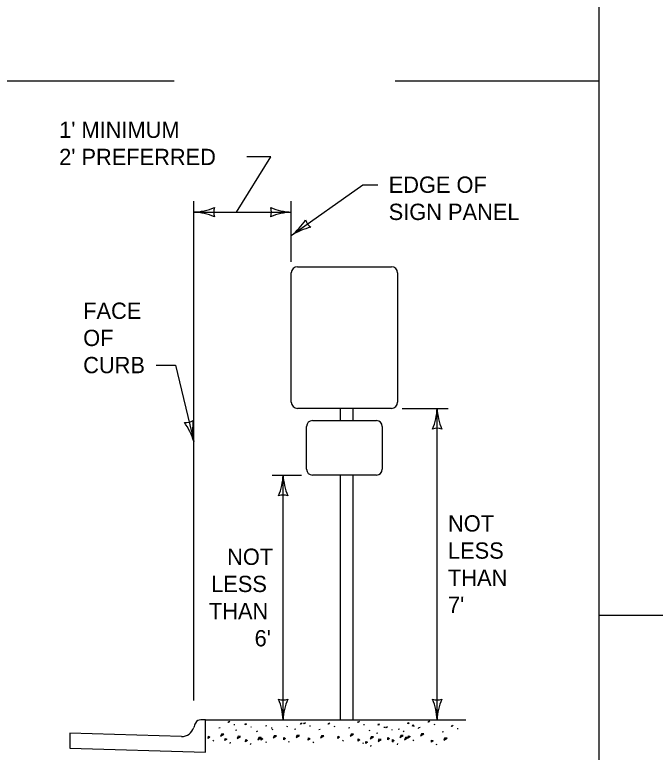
# Model space of a CAD drawing. Extents: x 49991.4 to 50021, y 49987.6 to 50011.4.
# Drawn here: x 50005.916 to 50008.274, y 49993.569 to 49996.284 of the extents above; entities that cross this region are included whole.
import ezdxf

# ---------------------------------------------------------------- set-up
doc = ezdxf.new("R2010")
doc.units = 0
for name, color, linetype in [('Level 1', 7, 'Continuous'), ('Level 2', 7, 'Continuous'), ('Level 3', 7, 'Continuous')]:
    doc.layers.add(name, color=color, linetype=linetype)

msp = doc.modelspace()

# ---------------------------------------------------------------- linework, layer by layer
at = {"layer": 'Level 1'}
for p, q in [((50006.9565, 49995.3563), (50007.3026, 49995.3563)), ((50006.934, 49994.8576), (50006.934, 49995.3338)), ((50007.3251, 49995.3338), (50007.3251, 49994.8576)), ((50007.3026, 49994.8351), (50006.9565, 49994.8351)), ((50007.1151, 49994.7902), (50007.1151, 49994.8351)), ((50007.1613, 49994.7902), (50007.1613, 49994.8351)), ((50006.9901, 49994.611), (50006.9901, 49994.7687)), ((50007.0116, 49994.7902), (50007.2476, 49994.7902)), ((50007.2691, 49994.7687), (50007.2691, 49994.611)), ((50007.2476, 49994.5895), (50007.0116, 49994.5895)), ((50007.1151, 49993.6882), (50007.1151, 49994.5895)), ((50007.1613, 49993.6882), (50007.1613, 49994.5895)), ((50006.6179, 49993.6882), (50006.6009, 49993.6882)), ((50006.6179, 49993.6882), (50007.5762, 49993.6882)), ((50006.6179, 49993.5697), (50006.6179, 49993.6882)), ((50006.7019, 49993.6784), (50006.7039, 49993.6831)), ((50006.7039, 49993.6831), (50006.7063, 49993.6795)), ((50007.1792, 49993.6784), (50007.1813, 49993.6831)), ((50007.1813, 49993.6831), (50007.1837, 49993.6795)), ((50007.4384, 49993.68), (50007.4404, 49993.6847)), ((50007.4429, 49993.681), (50007.4384, 49993.68)), ((50007.4404, 49993.6847), (50007.4429, 49993.681)), ((50006.6719, 49993.6588), (50006.6673, 49993.6573)), ((50006.7063, 49993.6795), (50006.7019, 49993.6784)), ((50006.7248, 49993.6688), (50006.7253, 49993.6724)), ((50006.7635, 49993.6704), (50006.7655, 49993.6751)), ((50006.7679, 49993.6715), (50006.7635, 49993.6704)), ((50006.7655, 49993.6751), (50006.7679, 49993.6715)), ((50006.7864, 49993.6608), (50006.7869, 49993.6644)), ((50006.8439, 49993.6667), (50006.8394, 49993.6656)), ((50006.8623, 49993.6561), (50006.8628, 49993.6597)), ((50006.9192, 49993.6625), (50006.9197, 49993.6661)), ((50006.9501, 49993.6541), (50006.9455, 49993.6525)), ((50006.9681, 49993.6721), (50006.9701, 49993.6768)), ((50006.9726, 49993.6732), (50006.9681, 49993.6721)), ((50006.9701, 49993.6768), (50006.9726, 49993.6732)), ((50006.9801, 49993.6736), (50006.9821, 49993.6784)), ((50006.9846, 49993.6747), (50006.9801, 49993.6736)), ((50006.9821, 49993.6784), (50006.9846, 49993.6747)), ((50007.003, 49993.6641), (50007.0035, 49993.6677)), ((50007.0702, 49993.6721), (50007.0722, 49993.6768)), ((50007.0747, 49993.6732), (50007.0702, 49993.6721)), ((50007.0722, 49993.6768), (50007.0747, 49993.6732)), ((50007.0931, 49993.6625), (50007.0936, 49993.6661)), ((50007.1493, 49993.6588), (50007.1446, 49993.6573)), ((50007.1837, 49993.6795), (50007.1792, 49993.6784)), ((50007.2021, 49993.6688), (50007.2026, 49993.6724)), ((50007.2536, 49993.6688), (50007.2556, 49993.6735)), ((50007.258, 49993.6699), (50007.2536, 49993.6688)), ((50007.2556, 49993.6735), (50007.258, 49993.6699)), ((50007.2765, 49993.6592), (50007.277, 49993.6629)), ((50007.2819, 49993.6593), (50007.284, 49993.6641)), ((50007.2864, 49993.6604), (50007.2819, 49993.6593)), ((50007.284, 49993.6641), (50007.2864, 49993.6604)), ((50007.3326, 49993.6541), (50007.328, 49993.6525)), ((50007.3626, 49993.6736), (50007.3646, 49993.6784)), ((50007.3671, 49993.6747), (50007.3626, 49993.6736)), ((50007.3646, 49993.6784), (50007.3671, 49993.6747)), ((50007.3799, 49993.6656), (50007.382, 49993.6704)), ((50007.3844, 49993.6667), (50007.3799, 49993.6656)), ((50007.382, 49993.6704), (50007.3844, 49993.6667)), ((50007.3855, 49993.6641), (50007.386, 49993.6677)), ((50007.4028, 49993.6561), (50007.4033, 49993.6597)), ((50007.4084, 49993.6604), (50007.4038, 49993.6588)), ((50007.4613, 49993.6704), (50007.4618, 49993.674)), ((50007.5238, 49993.6641), (50007.5258, 49993.6688)), ((50007.5283, 49993.6652), (50007.5238, 49993.6641)), ((50007.5258, 49993.6688), (50007.5283, 49993.6652)), ((50007.5467, 49993.6545), (50007.5472, 49993.6581)), ((50006.5296, 49993.6265), (50006.118, 49993.6388)), ((50006.118, 49993.6388), (50006.118, 49993.5846)), ((50006.6282, 49993.6199), (50006.6287, 49993.6282)), ((50006.6287, 49993.6282), (50006.6345, 49993.6249)), ((50006.6765, 49993.6358), (50006.6732, 49993.6279)), ((50006.6732, 49993.6279), (50006.6854, 49993.6356)), ((50006.6854, 49993.6356), (50006.6765, 49993.6358)), ((50006.7335, 49993.6508), (50006.7289, 49993.6493)), ((50006.7381, 49993.6278), (50006.7348, 49993.6199)), ((50006.7348, 49993.6199), (50006.747, 49993.6276)), ((50006.747, 49993.6276), (50006.7381, 49993.6278)), ((50006.8094, 49993.6461), (50006.8048, 49993.6445)), ((50006.8663, 49993.6525), (50006.8617, 49993.651)), ((50006.8709, 49993.6295), (50006.8676, 49993.6216)), ((50006.8676, 49993.6216), (50006.8798, 49993.6293)), ((50006.8798, 49993.6293), (50006.8709, 49993.6295)), ((50006.9547, 49993.6311), (50006.9514, 49993.6232)), ((50006.9514, 49993.6232), (50006.9636, 49993.6308)), ((50006.9636, 49993.6308), (50006.9547, 49993.6311)), ((50007.0402, 49993.6525), (50007.0356, 49993.651)), ((50007.0448, 49993.6295), (50007.0416, 49993.6216)), ((50007.0416, 49993.6216), (50007.0537, 49993.6293)), ((50007.0537, 49993.6293), (50007.0448, 49993.6295)), ((50007.1056, 49993.6199), (50007.1061, 49993.6282)), ((50007.1061, 49993.6282), (50007.1119, 49993.6249)), ((50007.1539, 49993.6358), (50007.1506, 49993.6279)), ((50007.1506, 49993.6279), (50007.1627, 49993.6356)), ((50007.1627, 49993.6356), (50007.1539, 49993.6358)), ((50007.2236, 49993.6493), (50007.219, 49993.6477)), ((50007.252, 49993.6398), (50007.2474, 49993.6382)), ((50007.3049, 49993.6498), (50007.3053, 49993.6534)), ((50007.3372, 49993.6311), (50007.334, 49993.6232)), ((50007.334, 49993.6232), (50007.3461, 49993.6308)), ((50007.3461, 49993.6308), (50007.3372, 49993.6311)), ((50007.35, 49993.6461), (50007.3454, 49993.6445)), ((50007.3648, 49993.6215), (50007.3653, 49993.6297)), ((50007.3711, 49993.6265), (50007.3648, 49993.6215)), ((50007.3653, 49993.6297), (50007.3711, 49993.6265)), ((50007.413, 49993.6374), (50007.4098, 49993.6295)), ((50007.4098, 49993.6295), (50007.4219, 49993.6371)), ((50007.4219, 49993.6371), (50007.413, 49993.6374)), ((50007.4938, 49993.6445), (50007.4892, 49993.643)), ((50006.6345, 49993.6249), (50006.6282, 49993.6199)), ((50006.647, 49993.6137), (50006.6455, 49993.6095)), ((50006.6898, 49993.6119), (50006.6903, 49993.6202)), ((50006.6962, 49993.6169), (50006.6898, 49993.6119)), ((50006.6903, 49993.6202), (50006.6962, 49993.6169)), ((50006.7086, 49993.6057), (50006.7071, 49993.6015)), ((50006.7658, 49993.6072), (50006.7663, 49993.6154)), ((50006.7721, 49993.6122), (50006.7658, 49993.6072)), ((50006.7663, 49993.6154), (50006.7721, 49993.6122)), ((50006.7846, 49993.601), (50006.783, 49993.5968)), ((50006.814, 49993.6231), (50006.8108, 49993.6152)), ((50006.8108, 49993.6152), (50006.8229, 49993.6228)), ((50006.8229, 49993.6228), (50006.814, 49993.6231)), ((50006.8226, 49993.6136), (50006.8231, 49993.6219)), ((50006.829, 49993.6186), (50006.8226, 49993.6136)), ((50006.8231, 49993.6219), (50006.829, 49993.6186)), ((50006.8414, 49993.6074), (50006.8399, 49993.6032)), ((50006.9065, 49993.6152), (50006.9069, 49993.6234)), ((50006.9128, 49993.6202), (50006.9065, 49993.6152)), ((50006.9069, 49993.6234), (50006.9128, 49993.6202)), ((50006.9252, 49993.609), (50006.9237, 49993.6048)), ((50006.9966, 49993.6136), (50006.997, 49993.6219)), ((50007.0029, 49993.6186), (50006.9966, 49993.6136)), ((50006.997, 49993.6219), (50007.0029, 49993.6186)), ((50007.0154, 49993.6074), (50007.0138, 49993.6032)), ((50007.1119, 49993.6249), (50007.1056, 49993.6199)), ((50007.1244, 49993.6137), (50007.1228, 49993.6095)), ((50007.1799, 49993.6103), (50007.1804, 49993.6186)), ((50007.1862, 49993.6153), (50007.1799, 49993.6103)), ((50007.1804, 49993.6186), (50007.1862, 49993.6153)), ((50007.1987, 49993.6042), (50007.1972, 49993.5999)), ((50007.2083, 49993.6009), (50007.2088, 49993.6091)), ((50007.2146, 49993.6059), (50007.2083, 49993.6009)), ((50007.2088, 49993.6091), (50007.2146, 49993.6059)), ((50007.2282, 49993.6262), (50007.2249, 49993.6183)), ((50007.2249, 49993.6183), (50007.2371, 49993.626)), ((50007.2371, 49993.626), (50007.2282, 49993.6262)), ((50007.2566, 49993.6168), (50007.2533, 49993.6089)), ((50007.2533, 49993.6089), (50007.2654, 49993.6165)), ((50007.2654, 49993.6165), (50007.2566, 49993.6168)), ((50007.289, 49993.6152), (50007.2895, 49993.6234)), ((50007.2953, 49993.6202), (50007.289, 49993.6152)), ((50007.2895, 49993.6234), (50007.2953, 49993.6202)), ((50007.3078, 49993.609), (50007.3062, 49993.6048)), ((50007.3063, 49993.6072), (50007.3068, 49993.6154)), ((50007.3126, 49993.6122), (50007.3063, 49993.6072)), ((50007.3068, 49993.6154), (50007.3126, 49993.6122)), ((50007.3251, 49993.601), (50007.3235, 49993.5968)), ((50007.3546, 49993.6231), (50007.3513, 49993.6152)), ((50007.3513, 49993.6152), (50007.3634, 49993.6228)), ((50007.3634, 49993.6228), (50007.3546, 49993.6231)), ((50007.3836, 49993.6153), (50007.382, 49993.6111)), ((50007.4501, 49993.6056), (50007.4506, 49993.6139)), ((50007.4565, 49993.6106), (50007.4501, 49993.6056)), ((50007.4506, 49993.6139), (50007.4565, 49993.6106)), ((50007.4689, 49993.5994), (50007.4674, 49993.5952)), ((50007.4984, 49993.6215), (50007.4951, 49993.6136)), ((50007.4951, 49993.6136), (50007.5073, 49993.6213)), ((50007.5073, 49993.6213), (50007.4984, 49993.6215)), ((50006.118, 49993.5846), (50006.6179, 49993.5697)), ((50007.2271, 49993.5947), (50007.2255, 49993.5904))]:
    msp.add_line(p, q, dxfattribs=at)
for centre, radius, start, end in [((50006.9565, 49995.3338), 0.0225, 90, 180), ((50007.3026, 49995.3338), 0.0225, 0, 90), ((50006.9565, 49994.8576), 0.0225, 180, 270), ((50007.3026, 49994.8576), 0.0225, 270, 0), ((50007.0116, 49994.7687), 0.0215, 90, 180), ((50007.2476, 49994.7687), 0.0215, 0, 90), ((50007.0116, 49994.611), 0.0215, 180, 270), ((50007.2476, 49994.611), 0.0215, 270, 0), ((50006.5993, 49993.6689), 0.0194, 85.3754, 156.6889), ((50006.5292, 49993.6742), 0.0477, 270.4937, 342.4535), ((50006.6257, 49993.6489), 0.0521, 148.469, 167.8949)]:
    msp.add_arc(centre, radius, start, end, dxfattribs=at)
at = {"layer": 'Level 3'}
for p, q in [((50008.0668, 49998.9992), (50008.0668, 49994.0732)), ((50005.0025, 49996.0407), (50006.5025, 49996.0407)), ((50007.3168, 49996.0407), (50008.0668, 49996.0407)), ((50006.7318, 49995.5574), (50006.8582, 49995.7607)), ((50006.8582, 49995.7607), (50006.7707, 49995.7607)), ((50006.934, 49995.4712), (50007.1971, 49995.6585)), ((50007.1971, 49995.6585), (50007.2525, 49995.6585)), ((50006.5747, 49993.7598), (50006.5747, 49995.5974)), ((50006.934, 49995.3751), (50006.934, 49995.5974)), ((50006.5747, 49995.5574), (50006.934, 49995.5574)), ((50006.4359, 49994.9945), (50006.5079, 49994.9945)), ((50006.5079, 49994.9945), (50006.5747, 49994.713)), ((50007.3426, 49994.8351), (50007.5109, 49994.8351)), ((50007.4709, 49993.6882), (50007.4709, 49994.8351)), ((50006.8638, 49994.5895), (50006.9716, 49994.5895)), ((50006.9038, 49993.6882), (50006.9038, 49994.5895)), ((50008.0668, 49994.0732), (50016.7501, 49994.0732)), ((50008.0668, 49994.0732), (50008.0668, 49987.7988))]:
    msp.add_line(p, q, dxfattribs=at)
for centre, radius, start, end in [((50006.5632, 49995.7901), 0.233, 272.8273, 292.0772), ((50006.5656, 49995.3353), 0.2223, 67.456, 87.6395), ((50006.7029, 49995.5574), 0.0548, 162.1388, 197.8612), ((50006.9432, 49995.7795), 0.2223, 247.456, 267.6395), ((50006.8058, 49995.5574), 0.0548, 342.1388, 17.8612), ((50006.9455, 49995.3247), 0.233, 92.8273, 112.0772), ((50006.7897, 49995.6541), 0.233, 308.2742, 327.5241), ((50007.0385, 49995.5455), 0.0548, 197.5858, 233.3081), ((50007.0554, 49995.2849), 0.2223, 102.9029, 123.0865), ((50007.2488, 49994.8443), 0.2223, 337.456, 357.6395), ((50007.7036, 49994.8466), 0.233, 182.8273, 202.0772), ((50006.5443, 49994.8376), 0.0548, 265.8498, 301.5721), ((50006.3514, 49994.6467), 0.233, 16.5382, 35.7881), ((50006.7927, 49994.7568), 0.2223, 171.1669, 191.3505), ((50007.4709, 49994.7069), 0.0548, 72.1388, 107.8612), ((50006.6817, 49994.5987), 0.2223, 337.456, 357.6395), ((50007.1365, 49994.601), 0.233, 182.8273, 202.0772), ((50006.9038, 49994.4613), 0.0548, 72.1388, 107.8612), ((50006.9038, 49993.8164), 0.0548, 252.1388, 287.8612), ((50006.6711, 49993.6767), 0.233, 2.8273, 22.0772), ((50007.1259, 49993.679), 0.2223, 157.456, 177.6395), ((50007.4709, 49993.8164), 0.0548, 252.1388, 287.8612), ((50007.2382, 49993.6767), 0.233, 2.8273, 22.0772), ((50007.693, 49993.679), 0.2223, 157.456, 177.6395)]:
    msp.add_arc(centre, radius, start, end, dxfattribs=at)

# ---------------------------------------------------------------- texts
at = {"layer": 'Level 2'}
for s, p in [("1' MINIMUM", (50006.0792, 49995.8307)), ("2' PREFERRED", (50006.0792, 49995.7307)), ('EDGE OF', (50007.2925, 49995.6285)), ('SIGN PANEL', (50007.2925, 49995.5285)), ('FACE', (50006.1677, 49995.1645)), ('OF', (50006.1677, 49995.0645)), ('CURB', (50006.1677, 49994.9645)), ('NOT', (50007.5109, 49994.3816)), ('LESS', (50007.5109, 49994.2816)), ('NOT', (50006.6977, 49994.2588)), ('THAN', (50007.5109, 49994.1816)), ('LESS', (50006.6389, 49994.1588)), ('THAN', (50006.6307, 49994.0588)), ("7'", (50007.5109, 49994.0816)), ("6'", (50006.7988, 49993.9588))]:
    msp.add_text(s, height=0.06, dxfattribs=at).set_placement(p)

doc.saveas('drawing.dxf')
